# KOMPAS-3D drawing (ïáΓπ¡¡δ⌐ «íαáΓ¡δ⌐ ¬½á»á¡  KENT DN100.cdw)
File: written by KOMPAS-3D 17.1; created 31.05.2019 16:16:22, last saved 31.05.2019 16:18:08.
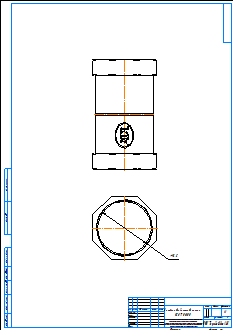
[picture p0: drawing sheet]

Sheet 1: A2, portrait

Title block, sheet 1: name: Латунный обратный клапан / KENT DN100; material: Внимание! Данный продукт является объектом авторского права ООО «Торговый Дом АДЛ». / Запрещается изменение, копирование, распространение / (в том числе путем копирования на другие сайты и ресурсы в Интернете) / или любое иное использование информации и объектов без предварительного / согласия правообладателя (ООО «Торговый Дом АДЛ»).; sheets: 1; organisation: ООО "Торговый дом АДЛ"; sheet format: A2

Views: Вид 1, Проекционный вид 2
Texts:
  user
Dimensions and other numbers on the sheet: 96,5; 1:1; 1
